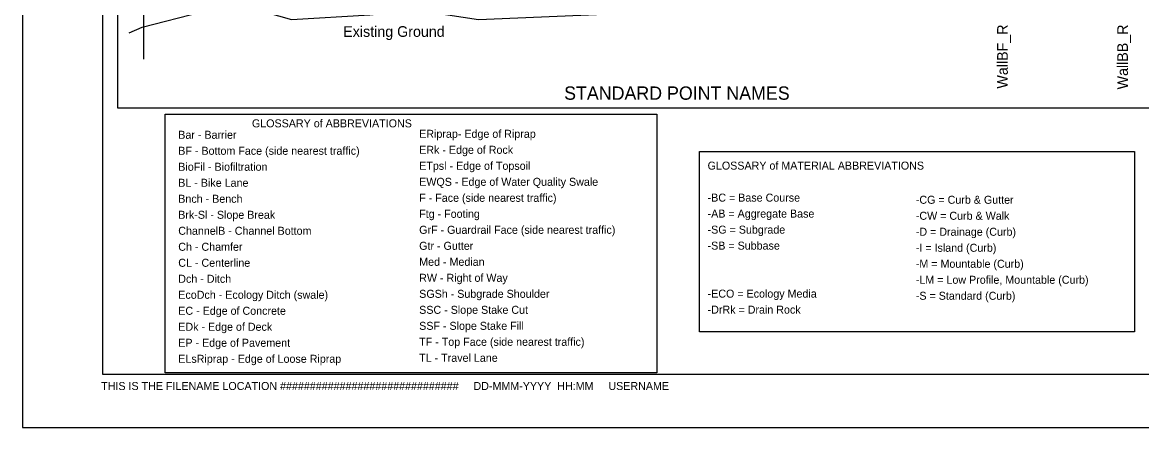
# Model space of a CAD drawing. Extents: x 0 to 1.42, y 0 to 0.92.
# Drawn here: x 0 to 0.874, y 0 to 0.317 of the extents above; entities that cross this region are included whole.
import ezdxf

# ---------------------------------------------------------------- set-up
doc = ezdxf.new("R2010")
doc.units = 0
for name, color, linetype in [('#plot_border', 7, 'Continuous'), ('#plot_shape', 7, 'Continuous'), ('Default', 7, 'Continuous'), ('Level 63', 7, 'Continuous'), ('P_ODOT_PLAN_Border', 7, 'Continuous'), ('P_RDWY_PLAN_Detail', 7, 'Continuous'), ('P_RDWY_PLAN_DetailTx', 7, 'Continuous')]:
    doc.layers.add(name, color=color, linetype=linetype)

msp = doc.modelspace()

# ---------------------------------------------------------------- linework, layer by layer
at = {"layer": '#plot_shape'}
msp.add_lwpolyline([(0, 0), (1.41667, 0), (1.41667, 0.91667), (0, 0.91667)], close=True, dxfattribs=at)
msp.add_lwpolyline([(0, 0), (1.41667, 0), (1.41667, 0.91667), (0, 0.91667)], close=True, dxfattribs=at)
at = {"layer": 'Level 63'}
for points in [[(0.91493, 0.24948), (0.07445, 0.24948), (0.07445, 0.86481), (0.91493, 0.86481)], [(0.86879, 0.07473), (0.52893, 0.07473), (0.52893, 0.21557), (0.86879, 0.21557)]]:
    msp.add_lwpolyline(points, close=True, dxfattribs=at)
at = {"layer": 'P_ODOT_PLAN_Border'}
msp.add_line((0.0625, 0.875), (0.0625, 0.0419), dxfattribs=at)
msp.add_line((0.0625, 0.875), (0.0625, 0.0419), dxfattribs=at)
msp.add_lwpolyline([(0.0625, 0.04167), (1.39583, 0.04167), (1.39583, 0.875), (0.0625, 0.875)], close=True, dxfattribs=at)
msp.add_lwpolyline([(0.0625, 0.04167), (1.39583, 0.04167), (1.39583, 0.875), (0.0625, 0.875)], close=True, dxfattribs=at)
msp.add_lwpolyline([(0.0625, 0.875), (0.0625, 0.875), (0.0625, 0.0419)], dxfattribs=at)
msp.add_lwpolyline([(0.0625, 0.875), (0.0625, 0.875), (0.0625, 0.0419)], dxfattribs=at)
at = {"layer": 'P_RDWY_PLAN_Detail'}
msp.add_lwpolyline([(0.08341, 0.30835), (0.09362, 0.31287), (0.14013, 0.32468), (0.18147, 0.32689), (0.21026, 0.31877), (0.27153, 0.32246), (0.30844, 0.32615), (0.35642, 0.31877), (0.44858, 0.3227), (0.57023, 0.38352), (0.66131, 0.38534)], dxfattribs=at)
msp.add_lwpolyline([(0.4955, 0.04274), (0.11148, 0.04274), (0.11148, 0.24476), (0.4955, 0.24476)], close=True, dxfattribs=at)
at = {"layer": 'P_RDWY_PLAN_DetailTx'}
msp.add_line((0.09483, 0.2878), (0.09483, 0.36902), dxfattribs=at)

# ---------------------------------------------------------------- texts
at = {"layer": '#plot_border'}
msp.add_text('THIS IS THE FILENAME LOCATION ##############################     DD-MMM-YYYY  HH:MM     USERNAME', height=0.00625, dxfattribs=at).set_placement((0.06153, 0.02939))
at = {"layer": 'Default'}
for s, p in [('-CG = Curb & Gutter', (0.6979, 0.17487)), ('-CW = Curb & Walk', (0.6979, 0.16237)), ('-D = Drainage (Curb)', (0.6979, 0.14987)), ('-I = Island (Curb)', (0.6979, 0.13737)), ('-M = Mountable (Curb)', (0.6979, 0.12487)), ('-LM = Low Profile, Mountable (Curb)', (0.6979, 0.11237)), ('-S = Standard (Curb)', (0.6979, 0.09987))]:
    msp.add_text(s, height=0.00625, dxfattribs=at).set_placement(p)
at = {"layer": 'P_RDWY_PLAN_DetailTx'}
for s, height, p in [('Existing Ground', 0.00833, (0.25063, 0.30526)), ('STANDARD POINT NAMES', 0.0104, (0.42319, 0.25611)), ('ERiprap- Edge of Riprap', 0.00625, (0.30996, 0.22639)), ('ERk - Edge of Rock', 0.00625, (0.30996, 0.21389)), ('ETpsl - Edge of Topsoil', 0.00625, (0.30996, 0.20139)), ('EWQS - Edge of Water Quality Swale', 0.00625, (0.30996, 0.18889)), ('F - Face (side nearest traffic)', 0.00625, (0.30996, 0.17639)), ('Ftg - Footing', 0.00625, (0.30996, 0.16389)), ('GrF - Guardrail Face (side nearest traffic)', 0.00625, (0.30996, 0.15139)), ('Gtr - Gutter', 0.00625, (0.30996, 0.13889)), ('Med - Median', 0.00625, (0.30996, 0.12639)), ('RW - Right of Way', 0.00625, (0.30996, 0.11389)), ('SGSh - Subgrade Shoulder', 0.00625, (0.30996, 0.10139)), ('SSC - Slope Stake Cut', 0.00625, (0.30996, 0.08889)), ('SSF - Slope Stake Fill', 0.00625, (0.30996, 0.07639)), ('TF - Top Face (side nearest traffic)', 0.00625, (0.30996, 0.06389)), ('TL - Travel Lane', 0.00625, (0.30996, 0.05139))]:
    msp.add_text(s, height=height, dxfattribs=at).set_placement(p)
for s, height, rotation, p in [('WallBF_R', 0.00833, 90, (0.76974, 0.26484)), ('WallBB_R', 0.00833, 90, (0.86362, 0.26418)), ('GLOSSARY of ABBREVIATIONS', 0.00625, 0.00001, (0.1793, 0.23456)), ('Bar - Barrier', 0.00625, 0.00001, (0.12177, 0.22564)), ('BF - Bottom Face (side nearest traffic)', 0.00625, 0.00001, (0.12177, 0.21314)), ('BioFil - Biofiltration', 0.00625, 0.00001, (0.12177, 0.20064)), ('GLOSSARY of MATERIAL ABBREVIATIONS', 0.00625, 0.00001, (0.53525, 0.20154)), ('BL - Bike Lane', 0.00625, 0.00001, (0.12177, 0.18814)), ('Bnch - Bench', 0.00625, 0.00001, (0.12177, 0.17564)), ('-BC = Base Course', 0.00625, 0.00001, (0.53525, 0.17654)), ('Brk-Sl - Slope Break', 0.00625, 0.00001, (0.12177, 0.16314)), ('-AB = Aggregate Base', 0.00625, 0.00001, (0.53525, 0.16404)), ('-SG = Subgrade', 0.00625, 0.00001, (0.53525, 0.15154)), ('ChannelB - Channel Bottom', 0.00625, 0.00001, (0.12177, 0.15064)), ('Ch - Chamfer', 0.00625, 0.00001, (0.12177, 0.13814)), ('-SB = Subbase', 0.00625, 0.00001, (0.53525, 0.13904)), ('CL - Centerline', 0.00625, 0.00001, (0.12177, 0.12564)), ('Dch - Ditch', 0.00625, 0.00001, (0.12177, 0.11314)), ('EcoDch - Ecology Ditch (swale)', 0.00625, 0.00001, (0.12177, 0.10064)), ('-ECO = Ecology Media', 0.00625, 0.00001, (0.53525, 0.10154)), ('EC - Edge of Concrete', 0.00625, 0.00001, (0.12177, 0.08814)), ('-DrRk = Drain Rock', 0.00625, 0.00001, (0.53525, 0.08904)), ('EDk - Edge of Deck', 0.00625, 0.00001, (0.12177, 0.07564)), ('EP - Edge of Pavement', 0.00625, 0.00001, (0.12177, 0.06314)), ('ELsRiprap - Edge of Loose Riprap', 0.00625, 0.00001, (0.12177, 0.05064))]:
    msp.add_text(s, height=height, rotation=rotation, dxfattribs=at).set_placement(p)

doc.saveas('drawing.dxf')
